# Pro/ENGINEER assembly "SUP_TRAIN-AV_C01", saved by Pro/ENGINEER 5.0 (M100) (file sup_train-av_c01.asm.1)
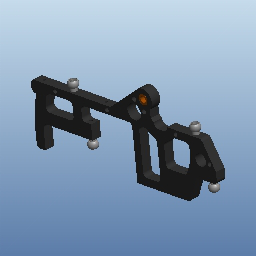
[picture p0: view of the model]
Units: millimeter Newton Second (mmNs); MM, TONNE, HOURS

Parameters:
  MC_INTF = "09/26/2011 269"

Other components: 80421700-PL_CELLULE-AV_C01, BAGUE_BASCULEUR_C01, E-ROTULE_VIS_C02, E-ROTULE_VIS_C02, E-ROTULE_VIS_C02, E-ROTULE_VIS_C02

Other named items: A-DROITE, A-DESSUS, A-FACE, A-R0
